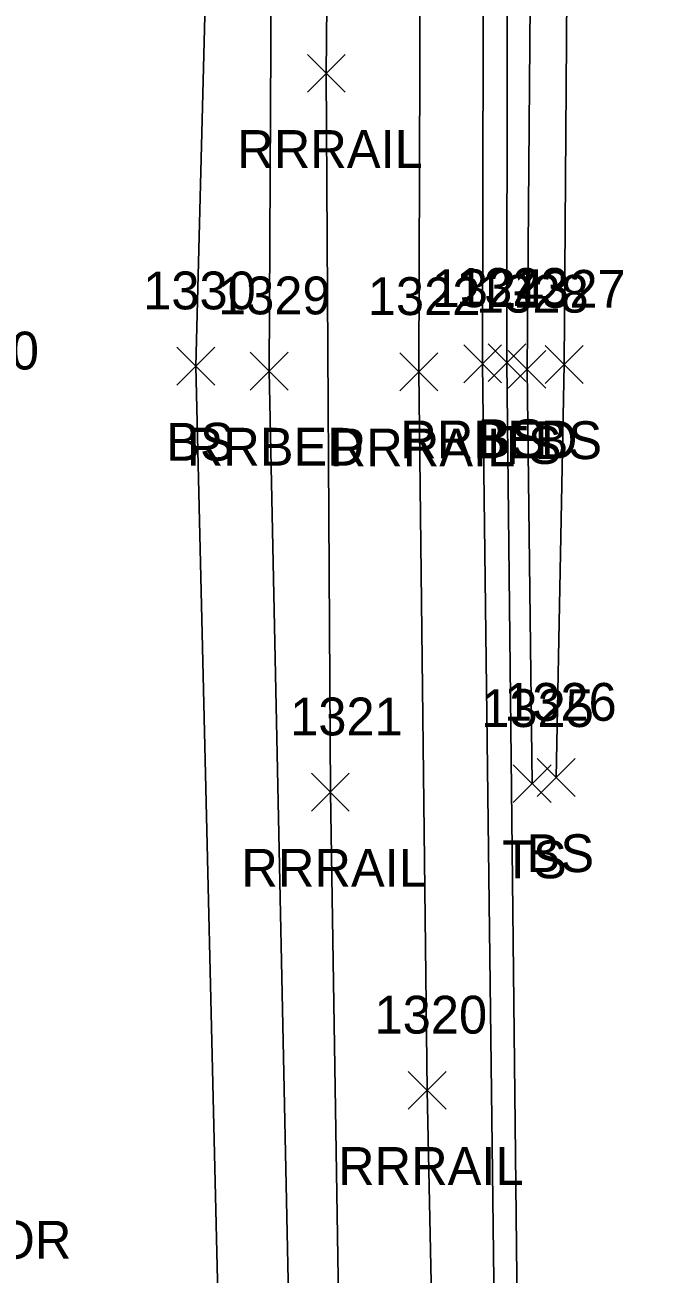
# Model space of a CAD drawing. Extents: x 1769141 to 1770817, y 735471 to 742405.
# Drawn here: x 1770137.4 to 1770171.2, y 741316.5 to 741382.5 of the extents above; entities that cross this region are included whole.
import ezdxf

# ---------------------------------------------------------------- set-up
doc = ezdxf.new("R2010")
doc.units = 0
for name, color, linetype in [('L_A', 7, 'Continuous'), ('L_I', 7, 'Continuous'), ('L_TIC', 7, 'Continuous'), ('LELB', 7, 'Continuous'), ('R_A', 7, 'Continuous'), ('R_I', 7, 'Continuous'), ('R_TIC', 7, 'Continuous'), ('RR', 7, 'Continuous'), ('RRB', 7, 'Continuous'), ('U_C', 7, 'Continuous')]:
    doc.layers.add(name, color=color, linetype=linetype)

msp = doc.modelspace()

# ---------------------------------------------------------------- linework, layer by layer
at = {"layer": 'L_TIC'}
for points in [[(1770145.463, 741363.503), (1770147.463, 741365.503)], [(1770147.463, 741363.503), (1770145.463, 741365.503)], [(1770161.911, 741363.686), (1770163.911, 741365.686)], [(1770163.911, 741363.686), (1770161.911, 741365.686)], [(1770162.973, 741363.331), (1770164.973, 741365.331)], [(1770164.973, 741363.331), (1770162.973, 741365.331)], [(1770164.93, 741363.586), (1770166.93, 741365.586)], [(1770166.93, 741363.586), (1770164.93, 741365.586)], [(1770164.509, 741341.748), (1770166.509, 741343.748)], [(1770166.509, 741341.748), (1770164.509, 741343.748)], [(1770163.245, 741341.42), (1770165.245, 741343.42)], [(1770165.245, 741341.42), (1770163.245, 741343.42)]]:
    msp.add_lwpolyline(points, dxfattribs=at)
at = {"layer": 'LELB'}
for points in [[(1770159.474, 741122.156), (1770155.885, 741129.719), (1770152.263, 741191.835), (1770148.79, 741250.944), (1770147.9, 741304.262), (1770146.463, 741364.503), (1770147.883, 741419.381), (1770149.7, 741479.08), (1770152.685, 741545.096), (1770155.759, 741599.645), (1770158.957, 741639.339), (1770162.272, 741670.364), (1770169.156, 741728.311), (1770174.079, 741769.967), (1770179.318, 741804.693), (1770187.632, 741847.878), (1770194.606, 741886.567)], [(1770170.717, 741118.889), (1770170.78, 741142.854), (1770168.078, 741192.95), (1770167.137, 741250.653), (1770163.559, 741305.093), (1770162.911, 741364.686), (1770162.954, 741418.416), (1770164.447, 741477.749), (1770168.472, 741544.612), (1770171.959, 741598.416), (1770177.164, 741637.544), (1770178.364, 741670.053), (1770184.179, 741725.156), (1770189.432, 741766.842), (1770194.193, 741801.424), (1770201.496, 741845.166), (1770207.418, 741883.863)], [(1770164.245, 741342.42), (1770163.973, 741364.331), (1770164.424, 741418.14), (1770165.95, 741478.004)], [(1770165.509, 741342.748), (1770165.93, 741364.586), (1770166.318, 741418.452), (1770165.95, 741478.004)]]:
    msp.add_lwpolyline(points, dxfattribs=at)
at = {"layer": 'R_TIC'}
for points in [[(1770152.361, 741378.981), (1770154.361, 741380.981)], [(1770154.361, 741378.981), (1770152.361, 741380.981)], [(1770149.339, 741363.239), (1770151.339, 741365.239)], [(1770151.339, 741363.239), (1770149.339, 741365.239)], [(1770160.626, 741363.619), (1770162.626, 741365.619)], [(1770162.626, 741363.619), (1770160.626, 741365.619)], [(1770157.249, 741363.202), (1770159.249, 741365.202)], [(1770159.249, 741363.202), (1770157.249, 741365.202)], [(1770152.579, 741340.976), (1770154.579, 741342.976)], [(1770154.579, 741340.976), (1770152.579, 741342.976)], [(1770157.691, 741325.209), (1770159.691, 741327.209)], [(1770159.691, 741325.209), (1770157.691, 741327.209)]]:
    msp.add_lwpolyline(points, dxfattribs=at)
at = {"layer": 'RR'}
for points in [[(1770158.416, 741192.158), (1770156.873, 741228.018), (1770155.371, 741265.978), (1770154.185, 741304.013), (1770153.579, 741341.976), (1770153.361, 741379.981), (1770153.719, 741418.087), (1770154.501, 741456.025), (1770155.71, 741494.067), (1770157.53, 741532.029), (1770159.75, 741569.97), (1770162.689, 741607.842), (1770166.022, 741645.783), (1770168.284, 741669.987)], [(1770164.281, 741173.164), (1770162.436, 741212.293), (1770160.947, 741250.165), (1770159.494, 741288.144), (1770158.691, 741326.209), (1770158.249, 741364.202), (1770158.38, 741402.169), (1770159.009, 741439.186), (1770160.275, 741478.161), (1770161.747, 741516.153), (1770163.249, 741544.577), (1770164.41, 741564.104), (1770166.37, 741592.001), (1770169.485, 741628.996), (1770173.058, 741667.734)]]:
    msp.add_lwpolyline(points, dxfattribs=at)
at = {"layer": 'RRB'}
for points in [[(1770159.474, 741122.156), (1770157.218, 741138.414), (1770154.835, 741192.111), (1770151.883, 741250.637), (1770151.589, 741304.352), (1770150.339, 741364.239), (1770150.632, 741419.356), (1770151.121, 741479.071), (1770155.019, 741545.103), (1770158.656, 741599.969), (1770162.08, 741639.219), (1770165.847, 741670.354), (1770171.873, 741726.988), (1770176.742, 741768.997), (1770181.566, 741804.321), (1770188.88, 741847.513), (1770194.606, 741886.567), (1770198.241, 741898.62)], [(1770170.717, 741118.889), (1770169.249, 741143.067), (1770166.386, 741192.947), (1770164.02, 741250.292), (1770162.365, 741304.755), (1770161.626, 741364.619), (1770161.725, 741418.126), (1770163.479, 741477.783), (1770166.119, 741544.523), (1770169.958, 741598.785), (1770173.919, 741637.727), (1770176.803, 741669.783), (1770182.941, 741725.601), (1770188.113, 741766.81), (1770193.154, 741801.759), (1770199.691, 741845.605), (1770207.418, 741883.863)]]:
    msp.add_lwpolyline(points, dxfattribs=at)

# ---------------------------------------------------------------- texts
at = {"layer": 'L_A'}
for s, p in [('BS', (1770144.904, 741359.503)), ('BS', (1770161.352, 741359.686)), ('TS', (1770162.382, 741359.331)), ('BS', (1770164.371, 741359.586)), ('BS', (1770163.95, 741337.748)), ('TS', (1770162.654, 741337.42))]:
    msp.add_text(s, height=2, dxfattribs=at).set_placement(p)
at = {"layer": 'L_I'}
for s, p in [('1330', (1770143.684, 741367.503)), ('1323', (1770160.219, 741367.686)), ('1328', (1770161.28, 741367.331)), ('1327', (1770163.237, 741367.586)), ('12610', (1770130.739, 741364.324)), ('1325', (1770161.552, 741345.42)), ('1326', (1770162.761, 741345.748))]:
    msp.add_text(s, height=2, dxfattribs=at).set_placement(p)
at = {"layer": 'R_A'}
for s, p in [('RRRAIL', (1770148.653, 741374.981)), ('RRBED', (1770157.271, 741359.619)), ('RRBED', (1770145.985, 741359.239)), ('RRRAIL', (1770153.54, 741359.202)), ('RRRAIL', (1770148.871, 741336.976)), ('RRRAIL', (1770153.982, 741321.209))]:
    msp.add_text(s, height=2, dxfattribs=at).set_placement(p)
at = {"layer": 'R_I'}
for s, p in [('1329', (1770147.639, 741367.239)), ('1322', (1770155.556, 741367.202)), ('1324', (1770158.933, 741367.619)), ('1321', (1770151.453, 741344.976)), ('1320', (1770155.912, 741329.209))]:
    msp.add_text(s, height=2, dxfattribs=at).set_placement(p)
at = {"layer": 'U_C'}
msp.add_text('MONITOR', height=2, dxfattribs=at).set_placement((1770127.261, 741317.306))

doc.saveas('drawing.dxf')
